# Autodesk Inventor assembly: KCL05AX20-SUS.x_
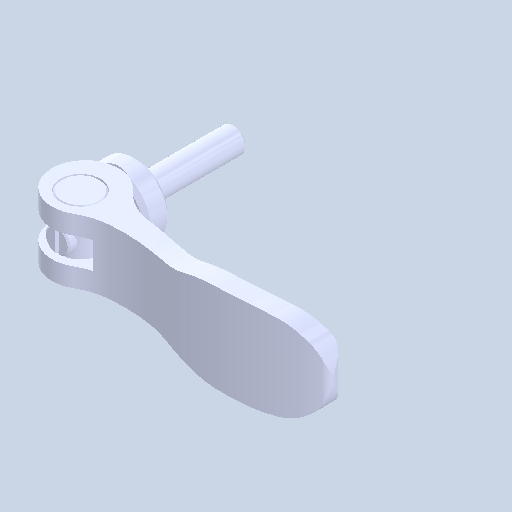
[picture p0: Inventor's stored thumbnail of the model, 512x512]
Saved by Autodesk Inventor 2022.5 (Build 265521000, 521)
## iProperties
Created: 2024-08
Part Number: KCL05AX20-SUS.x_
Document SubType Name: Assembly
Designer: ImaoCorp
Author: ImaoCorp
Sending System: SOLIDWORKS 2022-2022290
MC: AMD64
MC_MODEL: Intel64 Family 6 Model 60 Stepping 3, GenuineIntel
OS: Windows_NT
FRU: Parasolid Version 33.1, build 260,  4-25-2022
FORMAT: text
GUISE: transmit
KEY: FILEKCL05AX20-SUS.x_t
DATE: Thu Aug 29 10:48:29 2024
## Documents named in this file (5)
- Y:\5.更新分\2024年対応\1001_KCL\データ\kcl05ax20-sus\KCL05AX20-SUS.x_.iam
- Y:\5.更新分\2024年対応\1001_KCL\データ\kcl05ax20-sus\KCL05AX20-SUS_01.ipt
- Y:\5.更新分\2024年対応\1001_KCL\データ\kcl05ax20-sus\KCL05AX20-SUS_02.ipt
- Y:\5.更新分\2024年対応\1001_KCL\データ\kcl05ax20-sus\KCL05AX20-SUS_03.ipt
- Y:\5.更新分\2024年対応\1001_KCL\データ\kcl05ax20-sus\KCL05AX20-SUS_04.ipt
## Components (4 placed, 4 different names)
1. KCL05AX20-SUS_01
2. KCL05AX20-SUS_02
3. KCL05AX20-SUS_03
4. KCL05AX20-SUS_04
